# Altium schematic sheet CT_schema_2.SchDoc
size 366 x 279 mm
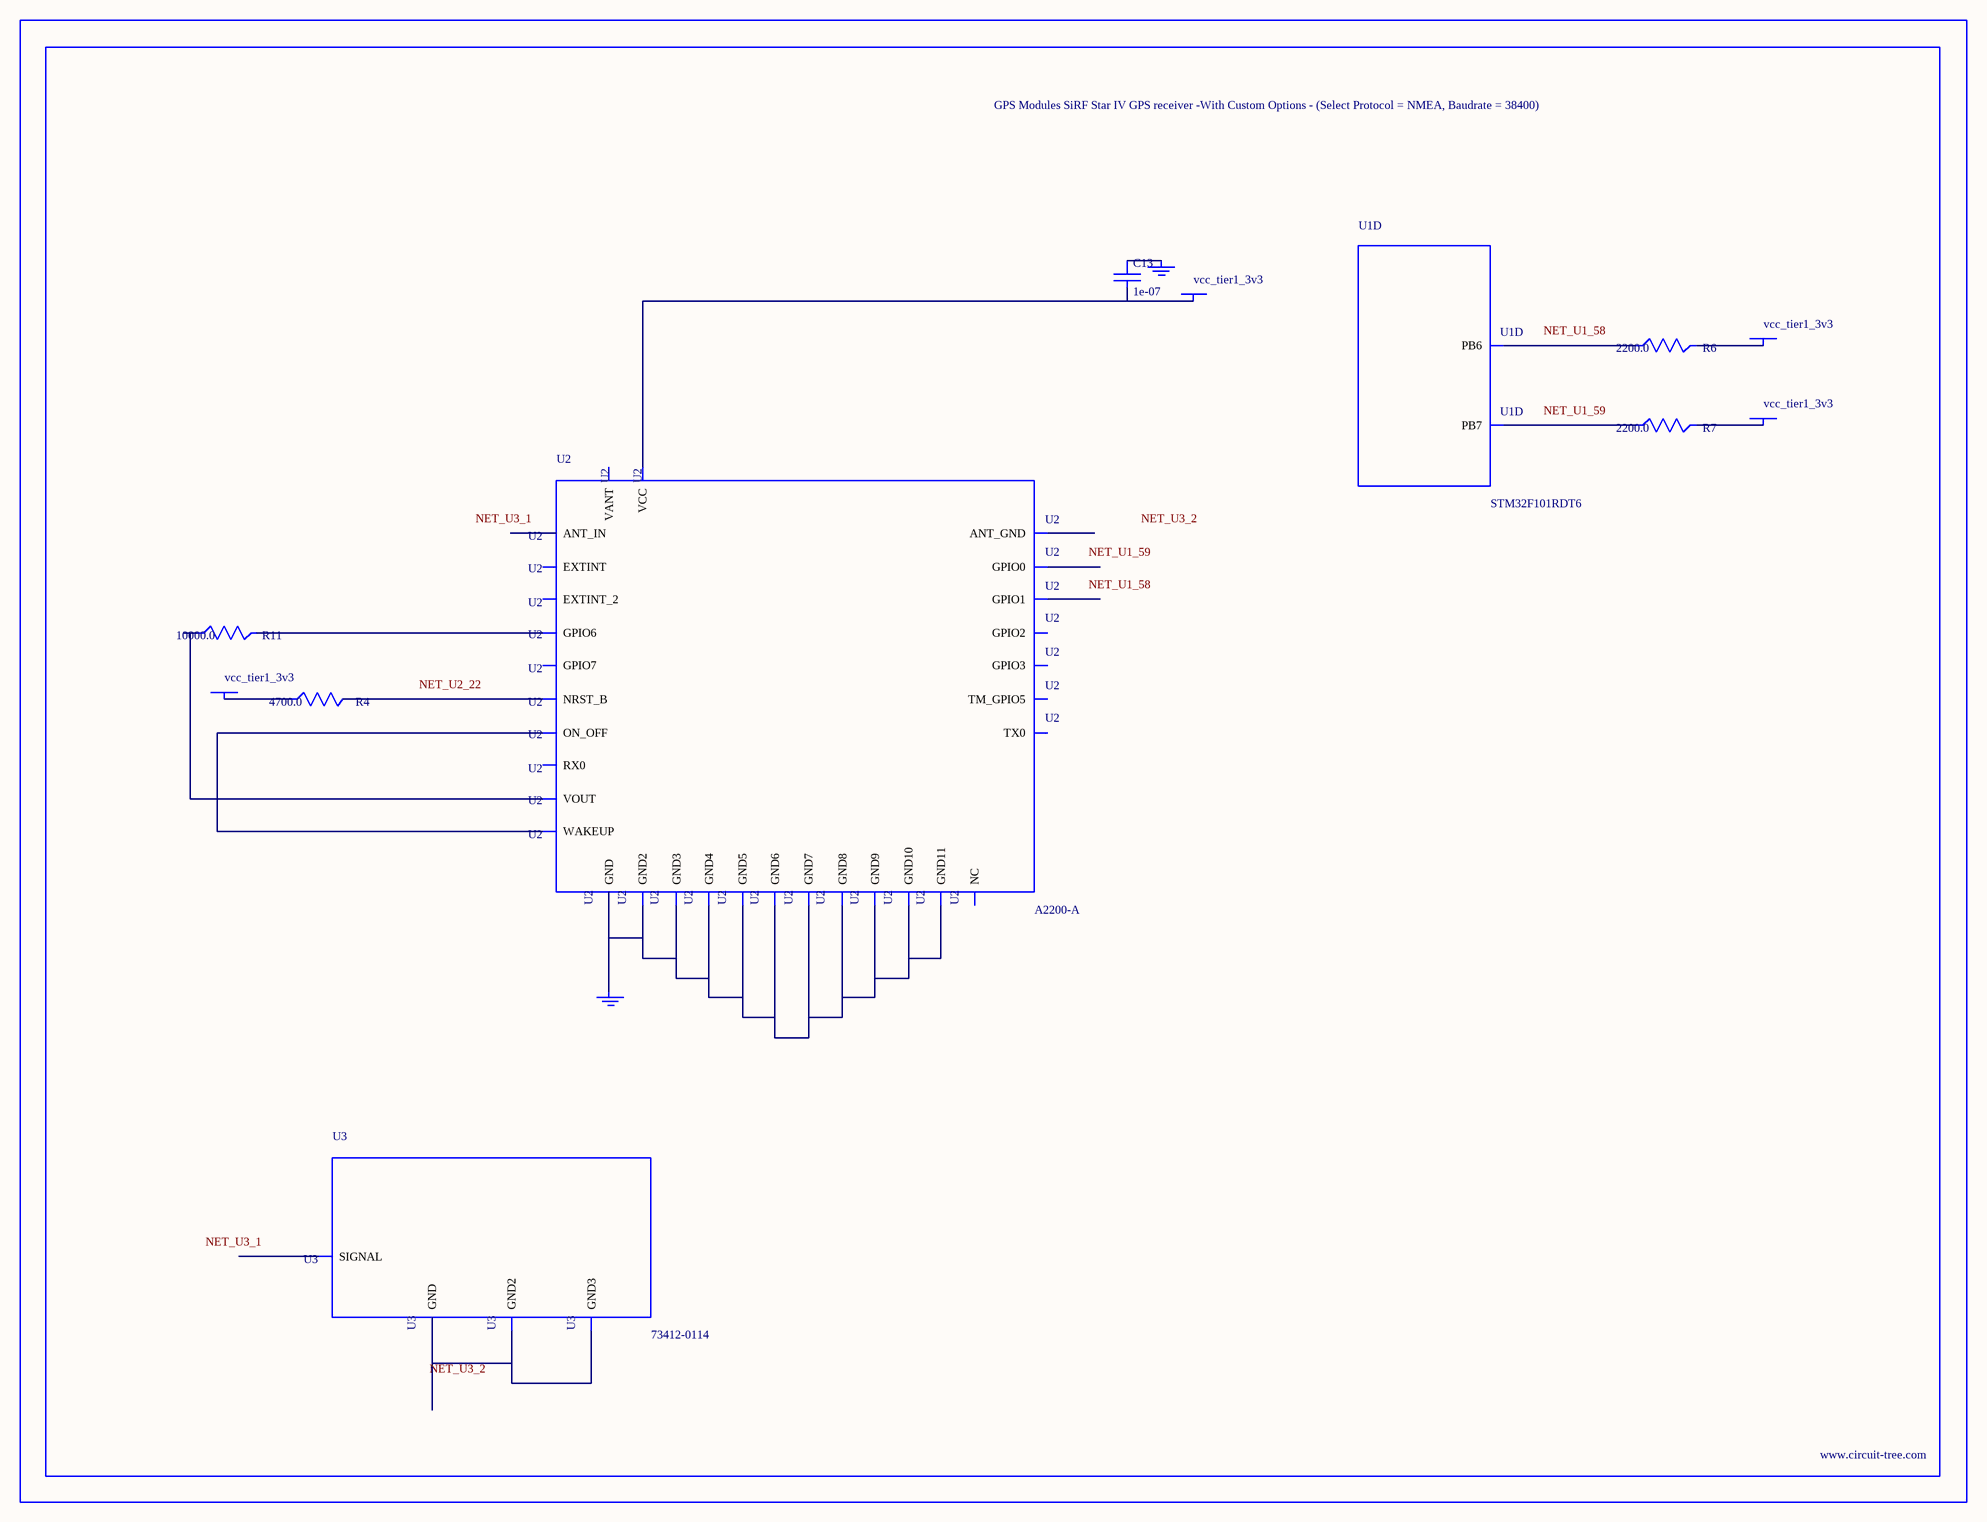
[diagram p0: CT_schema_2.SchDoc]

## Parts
BORDER1  (no value)
C13  1e-07  [C0402]
GND_INSTANCE_1_0  (no value)
GND_INSTANCE_1_1  (no value)
POWER_INSTANCE_1_0  vcc_tier1_3v3
POWER_INSTANCE_1_1  vcc_tier1_3v3
POWER_INSTANCE_1_2  vcc_tier1_3v3
POWER_INSTANCE_1_3  vcc_tier1_3v3
R4  4700.0  [R0603]
R6  2200.0  [R0603]
R7  2200.0  [R0603]
R11  10000.0  [R0603]
U1  STM32F101RDT6  [LQFP64]  (part D of 7)
U2  A2200-A  [A2200-A]
U3  73412-0114  [COAXIAL_C]

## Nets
NetC13_1: C13.1 GND_INSTANCE_1_0.0(GND)
NetC13_2: C13.2 POWER_INSTANCE_1_0.0(PWR) U2.20(VCC)
NetGND_INSTANCE_1_1_0: GND_INSTANCE_1_1.0(GND) U2.7(GND) U2.8(GND2) U2.23(GND3) U2.24(GND4) U2.25(GND5) U2.26(GND6) U2.27(GND7) U2.28(GND8) U2.29(GND9) U2.30(GND10) U2.31(GND11)
NetPOWER_INSTANCE_1_1_0: POWER_INSTANCE_1_1.0(PWR) R4.1
NetPOWER_INSTANCE_1_2_0: POWER_INSTANCE_1_2.0(PWR) R6.2
NetPOWER_INSTANCE_1_3_0: POWER_INSTANCE_1_3.0(PWR) R7.2
NetR4_2: R4.2 U2.22(NRST_B)
NetR6_1: R6.1 U1.58(PB6)
NetR7_1: R7.1 U1.59(PB7)
NetR11_1: R11.1 U2.2(VOUT)
NetR11_2: R11.2 U2.17(GPIO6)
NetU2_6: U2.6(ON_OFF) U2.19(WAKEUP)
NetU3_2: U3.2(GND) U3.3(GND2) U3.4(GND3)

Not connected (* = marked no-connect by the designer): U2 1(GPIO2) 3(TX0) 4(RX0) 5(EXTINT_2) 9(VANT) 10(ANT_GND) 11(ANT_IN) 12(GPIO3) 13(EXTINT) 14(TM_GPIO5) 15(GPIO1) 16(GPIO0) 18(GPIO7) 21(NC); U3 1(SIGNAL)

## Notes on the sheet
- Labels drawn without touching a wire or pin: NET_U1_58, NET_U1_59, NET_U2_22, NET_U3_1, NET_U3_2

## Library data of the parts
BORDER1 = BORDER_PAGE1
C13 = C0402C104K3RACTU
GND_INSTANCE_1_0 GND_INSTANCE_1_1 = GND
POWER_INSTANCE_1_0-POWER_INSTANCE_1_3 = PWR
R4 = RC0603JR-074K7L
R6 R7 = RC0603JR-072K2L
R11 = RC0603JR-0710KL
